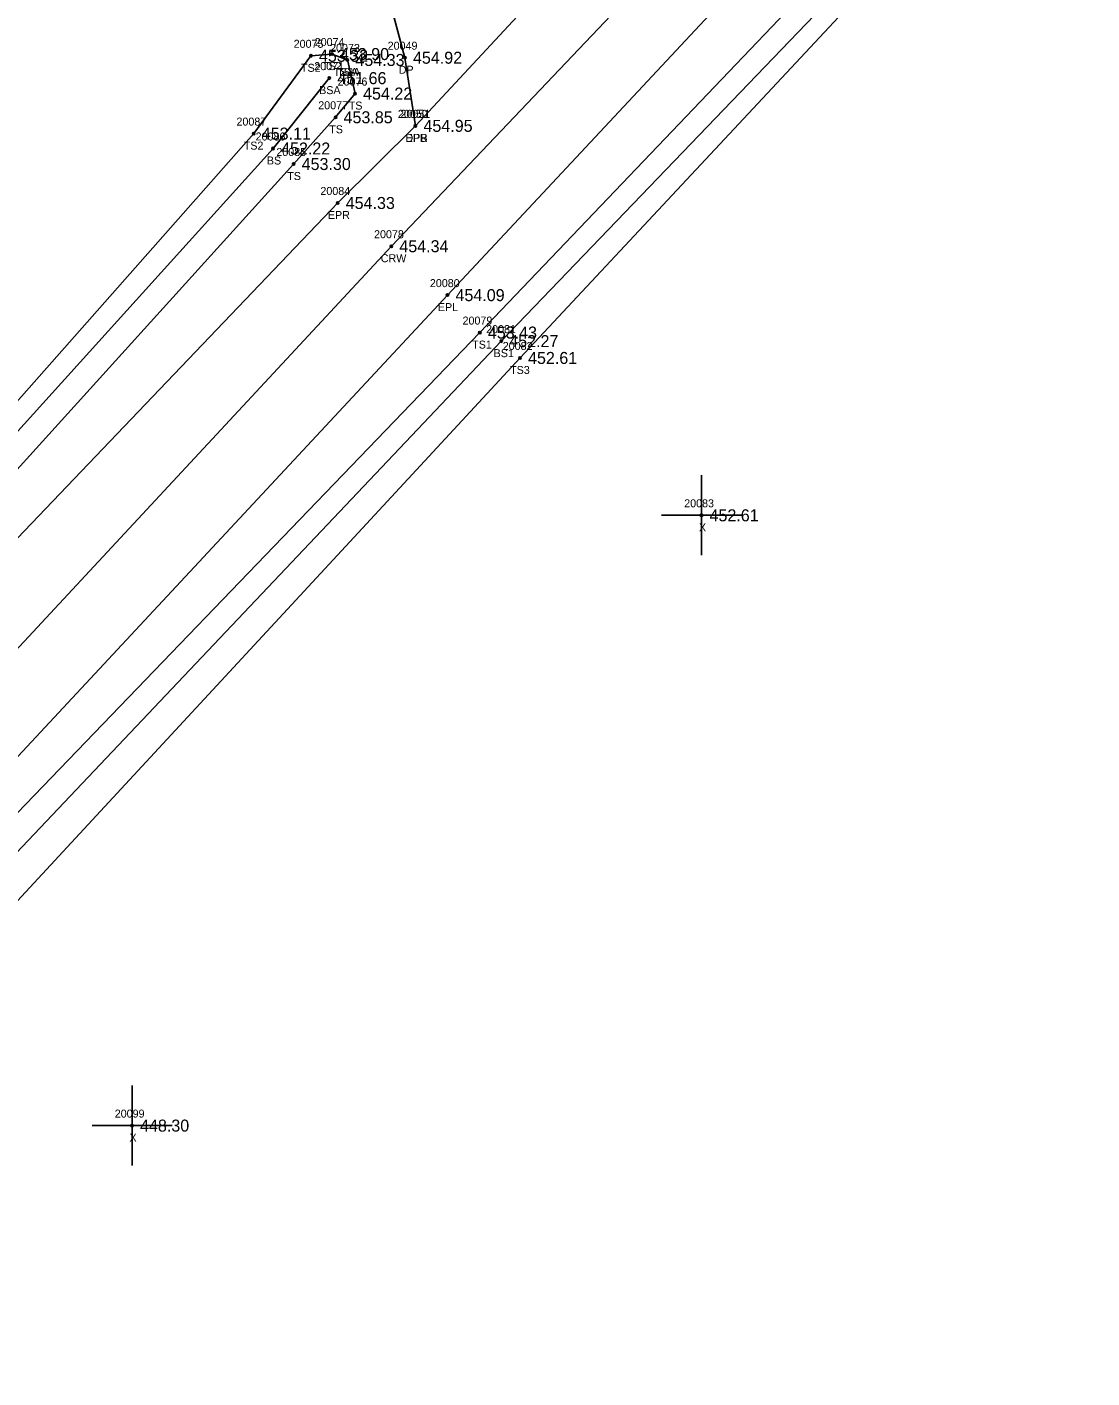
# Model space of a CAD drawing. Extents: x 1763022 to 1764007, y 824123 to 825394.
# Drawn here: x 1763705.9 to 1763838.9, y 824996 to 825164.8 of the extents above; entities that cross this region are included whole.
import ezdxf

# ---------------------------------------------------------------- set-up
doc = ezdxf.new("R2010")
doc.units = 0
for name, color, linetype in [('RD_DTM_BkLn1', 7, 'Continuous'), ('RD_DTM_BkLn2', 7, 'Continuous'), ('RD_DTM_BkLn_txCode', 7, 'Continuous'), ('RD_EX_Driveway', 7, 'Continuous'), ('RD_EX_Driveway_txCode', 7, 'Continuous'), ('RD_EX_Misc', 7, 'Continuous'), ('RD_EX_Misc_txCode', 7, 'Continuous'), ('RD_EX_Road', 7, 'Continuous'), ('RD_EX_Road_txCode', 7, 'Continuous'), ('RD_EX_TX_Driveway_ELEV', 7, 'Continuous'), ('RD_EX_TX_Misc_ELEV', 7, 'Continuous'), ('RD_EX_TX_Road_ELEV', 7, 'Continuous'), ('RD_HC_Survey_ELEV', 7, 'Continuous'), ('RD_HC_Survey_txCode', 7, 'Continuous'), ('RD_SMD_Locator', 7, 'Continuous')]:
    doc.layers.add(name, color=color, linetype=linetype)

msp = doc.modelspace()

# ---------------------------------------------------------------- linework, layer by layer
at = {"layer": 'RD_DTM_BkLn1'}
msp.add_lwpolyline([(1763957.85, 825358.99), (1763889.22, 825284.86), (1763820.79, 825210.5), (1763751.37, 825137.44), (1763682.52, 825063.34), (1763613.99, 824989.62), (1763581.46, 824952.08), (1763550.2, 824912.66), (1763519.29, 824872.78), (1763491.16, 824832.15)], dxfattribs=at)
at = {"layer": 'RD_DTM_BkLn2'}
for points in [[(1763968.07, 825349.7), (1763900.27, 825275.17), (1763832.66, 825200.26), (1763762.42, 825126.65), (1763692.83, 825054.38), (1763655.96, 825013.92), (1763657.67, 825011.86), (1763660.66, 825010.25)], [(1763969.49, 825348.41), (1763901.67, 825274.17), (1763835.08, 825198.5), (1763765.09, 825125.58), (1763695.51, 825052.15), (1763658.81, 825013.59)], [(1763971.84, 825347.08), (1763903.21, 825271.94), (1763836.32, 825197.24), (1763767.44, 825123.48), (1763698.39, 825048.89), (1763660.66, 825010.25)], [(1763745.88, 825160.71), (1763743.95, 825161.45), (1763741.33, 825161.23), (1763734.19, 825151.51), (1763667.93, 825076.53), (1763598.29, 825004), (1763566.28, 824964.92), (1763532.04, 824927.7), (1763520.45, 824914.1), (1763512.76, 824909.25), (1763510.52, 824906.49), (1763509.94, 824903.93)], [(1763745.88, 825160.71), (1763746.84, 825156.51), (1763744.4, 825153.55), (1763739.17, 825147.71), (1763672.03, 825073.56), (1763603.55, 824998.75), (1763569.03, 824962.49), (1763535.77, 824923.77), (1763524.58, 824910.39), (1763517.67, 824903.1), (1763511.98, 824902.34), (1763509.94, 824903.93)], [(1763743.62, 825158.44), (1763736.6, 825149.65), (1763669.73, 825075.6), (1763601.09, 825000.55), (1763567.43, 824963.88), (1763533.82, 824926.24), (1763521.76, 824912.79), (1763514.73, 824907.04), (1763512.63, 824905.46)]]:
    msp.add_lwpolyline(points, dxfattribs=at)
at = {"layer": 'RD_EX_Driveway'}
msp.add_lwpolyline([(1763784.22, 825184.64), (1763779.13, 825182.7), (1763772, 825181.08), (1763768.94, 825180.79), (1763766.91, 825181.97), (1763757.12, 825191.57), (1763744.73, 825180.98), (1763751.12, 825168.19), (1763753.07, 825160.99), (1763754.38, 825152.48)], dxfattribs=at)
at = {"layer": 'RD_EX_Misc'}
for p, q in [((1763790.1, 825098.82), (1763790.1, 825108.82)), ((1763785.1, 825103.82), (1763795.1, 825103.82)), ((1763718.99, 825022.57), (1763718.99, 825032.57)), ((1763713.99, 825027.57), (1763723.99, 825027.57))]:
    msp.add_line(p, q, dxfattribs=at)
at = {"layer": 'RD_EX_Road'}
for points in [[(1763951.03, 825365.44), (1763882.12, 825291.59), (1763813.3, 825217.44), (1763784.22, 825184.64), (1763754.38, 825152.48), (1763744.67, 825142.84), (1763675.27, 825070.17), (1763607.46, 824995.53), (1763574.27, 824958.09), (1763542.37, 824919.2), (1763512.11, 824877.96), (1763483.2, 824837.35)], [(1763963.89, 825353.59), (1763895.68, 825279.08), (1763827.34, 825205.22), (1763758.38, 825131.33), (1763689.43, 825057.33), (1763653.53, 825018.75), (1763637.74, 825000.8), (1763620.71, 824983.81), (1763588.78, 824946.6), (1763557.13, 824907.38), (1763526.52, 824867.67), (1763498.43, 824827.25)]]:
    msp.add_lwpolyline(points, dxfattribs=at)
at = {"layer": 'RD_SMD_Locator'}
for centre in [(1763741.33, 825161.23), (1763743.95, 825161.45), (1763753.07, 825160.99), (1763745.88, 825160.71), (1763745.88, 825160.71), (1763743.62, 825158.44), (1763746.84, 825156.51), (1763744.4, 825153.55), (1763754.38, 825152.48), (1763754.38, 825152.48), (1763734.19, 825151.51), (1763736.6, 825149.65), (1763739.17, 825147.71), (1763744.67, 825142.84), (1763751.37, 825137.44), (1763758.38, 825131.33), (1763762.42, 825126.65), (1763765.09, 825125.58), (1763767.44, 825123.48), (1763790.1, 825103.82), (1763718.99, 825027.57)]:
    msp.add_circle(centre, 0.15, dxfattribs=at)

# ---------------------------------------------------------------- texts
at = {"layer": 'RD_DTM_BkLn_txCode'}
for s, p in [('20075', (1763739.17, 825162.23)), ('20074', (1763741.8, 825162.45)), ('20072', (1763743.72, 825161.71)), ('20073', (1763743.72, 825161.71)), ('TS2', (1763740.09, 825159.23)), ('20071', (1763741.74, 825159.44)), ('TS2', (1763742.71, 825159.45)), ('TS2A', (1763744.15, 825158.71)), ('TSA', (1763744.6, 825158.71)), ('20076', (1763744.66, 825157.51)), ('BSA', (1763742.35, 825156.44)), ('20077', (1763742.24, 825154.55)), ('TS', (1763746.05, 825154.51)), ('20087', (1763732.03, 825152.51)), ('20086', (1763734.42, 825150.65)), ('TS', (1763743.61, 825151.55)), ('TS2', (1763732.94, 825149.51)), ('20085', (1763737.01, 825148.71)), ('BS', (1763735.82, 825147.65)), ('TS', (1763738.37, 825145.71)), ('20079', (1763760.26, 825127.65)), ('20081', (1763763.21, 825126.58)), ('TS1', (1763761.46, 825124.65)), ('BS1', (1763764.14, 825123.58)), ('20082', (1763765.28, 825124.48)), ('TS3', (1763766.2, 825121.48))]:
    msp.add_text(s, height=1, dxfattribs=at).set_placement(p)
at = {"layer": 'RD_EX_Driveway_txCode'}
for s, p in [('20049', (1763750.91, 825161.99)), ('DP', (1763752.29, 825158.99)), ('20050', (1763752.19, 825153.48)), ('DPB', (1763753.13, 825150.48))]:
    msp.add_text(s, height=1, dxfattribs=at).set_placement(p)
at = {"layer": 'RD_EX_Misc_txCode'}
for s, p in [('20083', (1763787.94, 825104.82)), ('X', (1763789.78, 825101.82)), ('20099', (1763716.83, 825028.57)), ('X', (1763718.67, 825025.57))]:
    msp.add_text(s, height=1, dxfattribs=at).set_placement(p)
at = {"layer": 'RD_EX_Road_txCode'}
for s, p in [('20051', (1763752.51, 825153.48)), ('EPR', (1763753.15, 825150.48)), ('20084', (1763742.51, 825143.84)), ('EPR', (1763743.44, 825140.84)), ('20080', (1763756.18, 825132.33)), ('EPL', (1763757.18, 825129.33))]:
    msp.add_text(s, height=1, dxfattribs=at).set_placement(p)
at = {"layer": 'RD_EX_TX_Driveway_ELEV'}
for s, p in [('454.92', (1763754.07, 825160.24)), ('454.95', (1763755.38, 825151.73))]:
    msp.add_text(s, height=1.5, dxfattribs=at).set_placement(p)
at = {"layer": 'RD_EX_TX_Misc_ELEV'}
for s, p in [('453.32', (1763742.33, 825160.48)), ('453.90', (1763744.95, 825160.7)), ('454.33', (1763746.88, 825159.96)), ('454.33', (1763746.88, 825159.96)), ('451.66', (1763744.62, 825157.69)), ('454.22', (1763747.84, 825155.76)), ('453.85', (1763745.4, 825152.8)), ('453.11', (1763735.19, 825150.76)), ('452.22', (1763737.6, 825148.9)), ('453.30', (1763740.17, 825146.96)), ('453.43', (1763763.42, 825125.9)), ('452.27', (1763766.09, 825124.83)), ('452.61', (1763768.44, 825122.73)), ('452.61', (1763791.1, 825103.07)), ('448.30', (1763719.99, 825026.82))]:
    msp.add_text(s, height=1.5, dxfattribs=at).set_placement(p)
at = {"layer": 'RD_EX_TX_Road_ELEV'}
for s, p in [('454.95', (1763755.38, 825151.73)), ('454.33', (1763745.67, 825142.09)), ('454.09', (1763759.38, 825130.58))]:
    msp.add_text(s, height=1.5, dxfattribs=at).set_placement(p)
at = {"layer": 'RD_HC_Survey_ELEV'}
msp.add_text('454.34', height=1.5, dxfattribs=at).set_placement((1763752.37, 825136.69))
at = {"layer": 'RD_HC_Survey_txCode'}
for s, p in [('20078', (1763749.21, 825138.44)), ('CRW', (1763750.05, 825135.44))]:
    msp.add_text(s, height=1, dxfattribs=at).set_placement(p)

doc.saveas('drawing.dxf')
